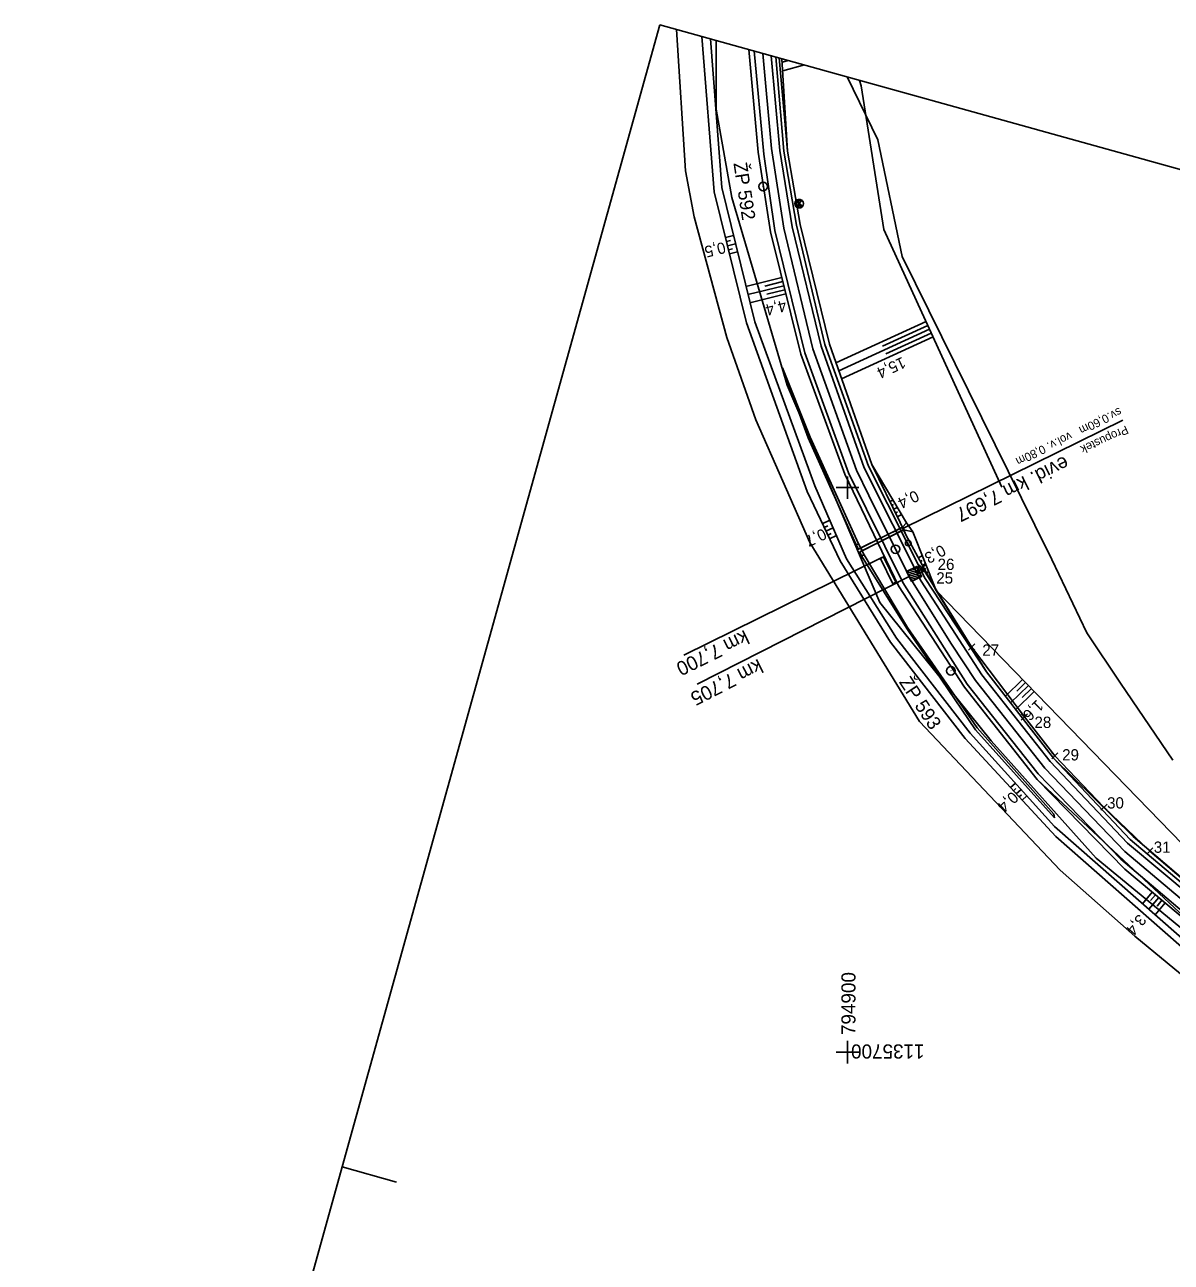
# Model space of a CAD drawing. Extents: x -795046 to -794647, y -1136002 to -1135518.
# Drawn here: x -795045.8 to -794842.7, y -1135737.2 to -1135518 of the extents above; entities that cross this region are included whole.
import ezdxf

# ---------------------------------------------------------------- set-up
doc = ezdxf.new("R2010")
doc.units = 0
for name, color, linetype in [('0381KM005-009P - Vrstva 1', 7, 'Continuous'), ('0381KM005-009P - Vrstva 13', 7, 'Continuous'), ('0381KM005-009P - Vrstva 19', 7, 'Continuous'), ('0381KM005-009P - Vrstva 28', 7, 'Continuous'), ('0381KM005-009P - Vrstva 3', 7, 'Continuous'), ('0381KM005-009P - Vrstva 4', 7, 'Continuous'), ('0381KM005-009P - Vrstva 48', 7, 'Continuous'), ('0381KM005-009P - Vrstva 49', 7, 'Continuous'), ('0381KM005-009P - Vrstva 51', 7, 'Continuous'), ('0381KM005-009P - Vrstva 55', 7, 'Continuous'), ('0381KM005-009P - Vrstva 7', 7, 'Continuous'), ('0381KM005-009P - Vrstva 9', 7, 'Continuous'), ('Default', 7, 'Continuous'), ('formát', 7, 'Continuous'), ('hran DP - hran DP', 7, 'Continuous'), ('krizky_1000 - souradnice', 7, 'Continuous'), ('krizky_1000 - Vrstva 1', 7, 'Continuous'), ('PSR_C2_1_Lomove_body_Strunkovice - Vrstva 60', 7, 'Continuous'), ('PSR_C2_1_trasa_Strunkovice - Kabelová trasa', 7, 'Continuous'), ('vyt_sit - stávající', 7, 'Continuous')]:
    doc.layers.add(name, color=color, linetype=linetype)

msp = doc.modelspace()

# ---------------------------------------------------------------- linework, layer by layer
at = {"layer": '0381KM005-009P - Vrstva 1'}
msp.add_lwpolyline([(-794915, -1135523.08), (-794913.46, -1135539.92), (-794911.29, -1135554.01), (-794906.18, -1135575.42), (-794898.43, -1135596.89), (-794896.25, -1135601.39), (-794889.11, -1135615.73), (-794881.58, -1135627.73), (-794877.36, -1135634.16), (-794865.05, -1135649.67), (-794850.87, -1135664.43), (-794835.06, -1135677.82), (-794817.77, -1135689.58), (-794801.57, -1135698.91), (-794785.04, -1135707.72), (-794765.11, -1135718.4), (-794746.17, -1135729.82), (-794729.27, -1135742.41), (-794716.02, -1135754.58), (-794701.99, -1135770.6), (-794697.2, -1135777.62)], dxfattribs=at)
at = {"layer": '0381KM005-009P - Vrstva 13'}
for points in [[(-794898.09, -1135609.93), (-794898.09, -1135609.93), (-794906.6, -1135591.05), (-794911.52, -1135578.79), (-794907, -1135591.18), (-794898.46, -1135610.15), (-794898.09, -1135609.93)], [(-794897.05, -1135611.89), (-794897.51, -1135612.1), (-794889.51, -1135624.97), (-794877.31, -1135642.92), (-794863.33, -1135658.49)], [(-794863.33, -1135658.49), (-794863.44, -1135657.81), (-794877.06, -1135642.57), (-794889.39, -1135624.78), (-794897.05, -1135611.89)]]:
    msp.add_lwpolyline(points, dxfattribs=at)
at = {"layer": '0381KM005-009P - Vrstva 19'}
for p, q in [((-794890.22, -1135607.23), (-794851.25, -1135588.05)), ((-794898.08, -1135610.9), (-794890.26, -1135606.98)), ((-794890.03, -1135607.47), (-794897.8, -1135611.38)), ((-794890.24, -1135606.98), (-794897.66, -1135610.68)), ((-794897.41, -1135611.19), (-794890.06, -1135607.43))]:
    msp.add_line(p, q, dxfattribs=at)
for points in [[(-794890.7, -1135606.17), (-794890.26, -1135606.98), (-794890.24, -1135606.98), (-794890.06, -1135607.43), (-794890.03, -1135607.47), (-794889.7, -1135608.37)], [(-794898.09, -1135609.93), (-794897.05, -1135611.89), (-794897.51, -1135612.1), (-794897.8, -1135611.38), (-794897.41, -1135611.19), (-794897.66, -1135610.68), (-794898.08, -1135610.9), (-794898.46, -1135610.15)]]:
    msp.add_lwpolyline(points, close=True, dxfattribs=at)
at = {"layer": '0381KM005-009P - Vrstva 28'}
msp.add_line((-794887.06, -1135614.6), (-794887.11, -1135614.51), dxfattribs=at)
msp.add_circle((-794887.08, -1135614.55), 0.5, dxfattribs=at)
at = {"layer": '0381KM005-009P - Vrstva 3'}
for p, q in [((-794889.11, -1135615.73), (-794926.66, -1135634.8)), ((-794886.88, -1135615.74), (-794889.56, -1135614.84)), ((-794887.35, -1135615.97), (-794889.32, -1135615.31)), ((-794887.11, -1135615.26), (-794889.08, -1135614.6)), ((-794887.83, -1135616.21), (-794889.08, -1135615.79)), ((-794888.3, -1135616.45), (-794888.85, -1135616.26)), ((-794887.35, -1135614.79), (-794888.61, -1135614.36)), ((-794887.58, -1135614.31), (-794888.13, -1135614.13))]:
    msp.add_line(p, q, dxfattribs=at)
msp.add_lwpolyline([(-794888.67, -1135616.63), (-794889.56, -1135614.84), (-794887.76, -1135613.95), (-794886.88, -1135615.74)], close=True, dxfattribs=at)
at = {"layer": '0381KM005-009P - Vrstva 4'}
for points in [[(-794917.47, -1135522.4), (-794915.85, -1135540.59), (-794913.67, -1135554.7), (-794908.27, -1135576.33), (-794900.49, -1135597.63), (-794890.98, -1135617.37), (-794879.27, -1135635.32), (-794866.44, -1135651.71), (-794836.69, -1135679.46), (-794818.84, -1135691.63), (-794786.57, -1135709.39), (-794766.3, -1135721.02), (-794748.58, -1135730.93), (-794731.42, -1135743.47), (-794717.51, -1135756.55), (-794703.68, -1135772.07), (-794698, -1135780.52)], [(-794697.72, -1135779.5), (-794703.02, -1135771.54), (-794717.11, -1135755.66), (-794731.12, -1135742.73), (-794748.15, -1135730.35), (-794763.88, -1135720.89), (-794786.11, -1135708.79), (-794818.08, -1135691.13), (-794836.08, -1135678.99), (-794851.61, -1135665.79), (-794866.22, -1135650.67), (-794878.82, -1135634.83), (-794890.24, -1135616.8), (-794899.85, -1135597.37), (-794907.59, -1135576.09), (-794912.87, -1135554.46), (-794914.85, -1135540.94), (-794916.58, -1135522.65)], [(-794696.7, -1135775.84), (-794700.88, -1135769.71), (-794714.51, -1135754.08), (-794728.76, -1135740.91), (-794743.23, -1135730.04), (-794762.73, -1135718.04), (-794783.1, -1135707.11), (-794816.84, -1135688.49), (-794833.24, -1135677.32), (-794850.38, -1135662.96), (-794864.1, -1135648.49), (-794876.22, -1135633.13), (-794886.94, -1135616.58), (-794897.05, -1135596.51), (-794904.69, -1135574.95), (-794909.82, -1135553.82), (-794912.02, -1135540.3), (-794913.51, -1135523.5)], [(-794912.74, -1135523.71), (-794911.32, -1135540.41), (-794909.07, -1135553.52), (-794904.05, -1135574.62), (-794896.27, -1135596.21), (-794886.26, -1135616.08), (-794875.38, -1135632.64), (-794863.5, -1135647.94), (-794849.93, -1135662.35), (-794832.65, -1135676.88), (-794816.85, -1135687.92), (-794782.78, -1135706.49), (-794762.23, -1135717.77), (-794742.47, -1135729.7), (-794727.73, -1135739.54), (-794713.83, -1135753.13), (-794700.2, -1135769.22), (-794696.4, -1135774.74)]]:
    msp.add_lwpolyline(points, dxfattribs=at)
at = {"layer": '0381KM005-009P - Vrstva 48'}
for p, q in [((-794910.48, -1135524.34), (-794911.58, -1135524.64)), ((-794907.65, -1135525.13), (-794911.49, -1135526.17)), ((-794921.65, -1135555.69), (-794920.21, -1135555.33)), ((-794921.47, -1135556.42), (-794920.75, -1135556.24)), ((-794921.29, -1135557.15), (-794919.85, -1135556.79)), ((-794921.11, -1135557.88), (-794920.39, -1135557.7)), ((-794920.93, -1135558.6), (-794919.5, -1135558.25)), ((-794911.66, -1135562.77), (-794918.01, -1135564.35)), ((-794911.47, -1135563.49), (-794914.65, -1135564.29)), ((-794911.29, -1135564.22), (-794917.65, -1135565.81)), ((-794910.93, -1135565.68), (-794917.29, -1135567.27)), ((-794911.11, -1135564.95), (-794914.29, -1135565.74)), ((-794886.1, -1135570.57), (-794902.06, -1135577.88)), ((-794885.48, -1135571.93), (-794901.56, -1135579.3)), ((-794885.79, -1135571.25), (-794893.8, -1135574.92)), ((-794884.85, -1135573.3), (-794901.06, -1135580.72)), ((-794885.17, -1135572.61), (-794893.24, -1135576.31)), ((-794892.51, -1135602.47), (-794891.95, -1135602.19)), ((-794892.18, -1135603.14), (-794891.87, -1135602.99)), ((-794891.85, -1135603.81), (-794891.18, -1135603.49)), ((-794891.52, -1135604.49), (-794891.16, -1135604.31)), ((-794891.19, -1135605.16), (-794890.41, -1135604.78)), ((-794904.48, -1135606.38), (-794903.16, -1135605.75)), ((-794904.16, -1135607.05), (-794903.51, -1135606.74)), ((-794903.83, -1135607.73), (-794902.56, -1135607.12)), ((-794903.51, -1135608.41), (-794902.89, -1135608.11)), ((-794903.19, -1135609.08), (-794901.96, -1135608.5)), ((-794887.47, -1135612.45), (-794886.76, -1135612.05)), ((-794887.11, -1135613.1), (-794886.8, -1135612.93)), ((-794886.75, -1135613.76), (-794886.2, -1135613.46)), ((-794886.39, -1135614.42), (-794886.16, -1135614.29)), ((-794886.03, -1135615.08), (-794885.64, -1135614.87)), ((-794869.01, -1135633.98), (-794872.05, -1135636.93)), ((-794867.96, -1135635.05), (-794871.12, -1135638.12)), ((-794868.48, -1135634.52), (-794870.03, -1135636.02)), ((-794867.44, -1135635.59), (-794869.05, -1135637.16)), ((-794866.92, -1135636.13), (-794870.2, -1135639.31)), ((-794871.13, -1135653.14), (-794870.27, -1135652.34)), ((-794870.62, -1135653.69), (-794870.19, -1135653.29)), ((-794870.11, -1135654.24), (-794869.27, -1135653.46)), ((-794869.6, -1135654.79), (-794869.18, -1135654.4)), ((-794869.09, -1135655.34), (-794868.26, -1135654.56)), ((-794846.02, -1135671.64), (-794847.73, -1135673.69)), ((-794844.87, -1135672.6), (-794846.61, -1135674.68)), ((-794845.45, -1135672.12), (-794846.31, -1135673.15)), ((-794844.3, -1135673.09), (-794845.17, -1135674.13)), ((-794843.72, -1135673.57), (-794845.48, -1135675.67))]:
    msp.add_line(p, q, dxfattribs=at)
at = {"layer": '0381KM005-009P - Vrstva 49'}
for p, q in [((-794912.11, -1135523.89), (-794910.64, -1135540.4)), ((-794890.7, -1135606.17), (-794890.26, -1135606.98)), ((-794890.26, -1135606.98), (-794889.55, -1135606.22)), ((-794890.03, -1135607.47), (-794888.43, -1135607.82)), ((-794889.7, -1135608.37), (-794890.03, -1135607.47))]:
    msp.add_line(p, q, dxfattribs=at)
for points in [[(-794925.83, -1135520.07), (-794923.66, -1135547.6), (-794917.9, -1135570.81), (-794907.19, -1135600.69), (-794901.33, -1135612.99), (-794892.4, -1135627.36), (-794879.19, -1135644.46), (-794863.1, -1135661.78), (-794838.91, -1135683.03), (-794815.97, -1135701.12), (-794794.79, -1135715.61), (-794782.46, -1135721.1), (-794767.75, -1135725.5), (-794750.75, -1135732.17), (-794732.98, -1135744.75), (-794719.14, -1135757.73), (-794705.45, -1135773.64), (-794699.07, -1135784.37)], [(-794749.75, -1135730.99), (-794767.46, -1135724.56), (-794782.23, -1135720.17), (-794794.11, -1135714.55), (-794814.96, -1135700.02), (-794837.43, -1135682.73), (-794863.32, -1135660), (-794878.31, -1135643.5), (-794891.31, -1135626.67), (-794900.17, -1135612.61), (-794905.81, -1135599.68), (-794916.46, -1135570.65), (-794922.29, -1135546.83), (-794924.31, -1135520.49)], [(-794917.47, -1135522.4), (-794915.85, -1135540.59), (-794913.67, -1135554.7), (-794908.27, -1135576.33), (-794900.49, -1135597.63), (-794890.98, -1135617.37), (-794879.27, -1135635.32), (-794866.44, -1135651.71), (-794850.9, -1135667.56)], [(-794911.62, -1135524.02), (-794910.64, -1135540.4), (-794908.42, -1135553.38), (-794903.23, -1135574.56), (-794895.71, -1135595.89), (-794889.55, -1135606.22), (-794888.43, -1135607.82), (-794884.32, -1135618.22)], [(-794897.87, -1135527.85), (-794897.6, -1135528.83), (-794893.57, -1135554.26), (-794872.65, -1135599.94)], [(-794895.71, -1135595.89), (-794890.7, -1135606.17)], [(-794889.7, -1135608.37), (-794884.32, -1135618.22), (-794824.85, -1135679.44), (-794811.36, -1135687.77), (-794786.09, -1135699.38), (-794707.09, -1135741.45)], [(-794863.5, -1135647.94), (-794875.38, -1135632.64), (-794884.32, -1135618.22)], [(-794695.93, -1135773.08), (-794698.78, -1135768.51), (-794712.94, -1135751.52), (-794727.73, -1135739.54), (-794743.72, -1135728.23), (-794763.92, -1135716.02), (-794781.48, -1135706.54), (-794800.89, -1135696.32), (-794816.57, -1135687.28), (-794832.17, -1135676.47), (-794849.4, -1135661.77), (-794863.5, -1135647.94)], [(-794850.9, -1135667.56), (-794836.69, -1135679.46), (-794818.84, -1135691.63), (-794803.16, -1135702.98), (-794784.32, -1135712.45), (-794768.51, -1135721.35), (-794758.17, -1135725.72), (-794749.71, -1135730.94)]]:
    msp.add_lwpolyline(points, dxfattribs=at)
at = {"layer": '0381KM005-009P - Vrstva 51'}
msp.add_lwpolyline([(-794699.07, -1135784.37), (-794705.45, -1135773.64), (-794719.14, -1135757.73), (-794732.98, -1135744.75), (-794750.75, -1135732.17), (-794767.75, -1135725.5), (-794782.46, -1135721.1), (-794794.79, -1135715.61), (-794815.97, -1135701.12), (-794838.91, -1135683.03), (-794863.1, -1135661.78), (-794879.19, -1135644.46), (-794892.4, -1135627.36), (-794901.33, -1135612.99), (-794907.19, -1135600.69), (-794917.9, -1135570.81), (-794923.66, -1135547.6), (-794925.83, -1135520.07)], dxfattribs=at)
at = {"layer": '0381KM005-009P - Vrstva 55'}
msp.add_lwpolyline([(-794930.32, -1135518.82), (-794928.69, -1135543.86), (-794927.18, -1135552.03), (-794921.37, -1135573.41), (-794916.26, -1135587.98), (-794906.67, -1135609.69), (-794887.27, -1135641.42), (-794862.33, -1135667.74), (-794849.1, -1135679.42), (-794837.63, -1135688.88), (-794826.42, -1135697.51), (-794808.25, -1135711.35), (-794792.02, -1135721.49), (-794781.13, -1135725.75), (-794765.57, -1135730.81), (-794749.96, -1135737.95), (-794742.14, -1135743.85), (-794737.72, -1135738.96), (-794727.83, -1135728.01), (-794718.43, -1135717.37), (-794692.54, -1135688.86), (-794715.68, -1135650.06)], dxfattribs=at)
at = {"layer": '0381KM005-009P - Vrstva 7'}
msp.add_line((-794889.24, -1135609.86), (-794889.28, -1135609.77), dxfattribs=at)
for centre, radius in [((-794889.26, -1135609.81), 0.5), ((-794891.51, -1135610.91), 0.75)]:
    msp.add_circle(centre, radius, dxfattribs=at)
at = {"layer": '0381KM005-009P - Vrstva 9'}
for p, q in [((-794893.93, -1135612.39), (-794929, -1135629.69)), ((-794894.19, -1135612.52), (-794894.73, -1135612.79)), ((-794893.66, -1135612.26), (-794894.19, -1135612.52)), ((-794894.19, -1135612.52), (-794892, -1135617.01)), ((-794891.46, -1135616.75), (-794893.66, -1135612.26)), ((-794892, -1135617.01), (-794891.46, -1135616.75))]:
    msp.add_line(p, q, dxfattribs=at)
at = {"layer": 'formát'}
for p, q in [((-794933.28, -1135518), (-794989.53, -1135720.33)), ((-794933.28, -1135518), (-794647.13, -1135597.56)), ((-794989.53, -1135720.33), (-795045.79, -1135922.65)), ((-794989.53, -1135720.33), (-794979.9, -1135723.01))]:
    msp.add_line(p, q, dxfattribs=at)
at = {"layer": 'hran DP - hran DP'}
for p, q in [((-794923.29, -1135532.94), (-794923.3, -1135520.77)), ((-794900.1, -1135527.22), (-794894.63, -1135538.4)), ((-794920.48, -1135548.58), (-794923.29, -1135532.94)), ((-794894.63, -1135538.4), (-794890.34, -1135559.06)), ((-794910.72, -1135581.84), (-794920.48, -1135548.58)), ((-794890.34, -1135559.06), (-794866.81, -1135606.62)), ((-794894.27, -1135620.34), (-794910.72, -1135581.84)), ((-794866.81, -1135606.62), (-794863.8, -1135612.72)), ((-794863.8, -1135612.72), (-794857.64, -1135625.71)), ((-794874.54, -1135644.85), (-794894.27, -1135620.34)), ((-794857.64, -1135625.71), (-794851.67, -1135634.62)), ((-794851.67, -1135634.62), (-794842.4, -1135648.25)), ((-794855.96, -1135665.64), (-794874.54, -1135644.85)), ((-794807.25, -1135705.8), (-794855.96, -1135665.64))]:
    msp.add_line(p, q, dxfattribs=at)
at = {"layer": 'krizky_1000 - Vrstva 1'}
for points in [[(-794900, -1135598), (-794900, -1135602)], [(-794902, -1135600), (-794898, -1135600)], [(-794900, -1135698), (-794900, -1135702)], [(-794902, -1135700), (-794898, -1135700)]]:
    msp.add_lwpolyline(points, dxfattribs=at)
at = {"layer": 'PSR_C2_1_Lomove_body_Strunkovice - Vrstva 60'}
for p, q in [((-794887.54, -1135614.93), (-794886.44, -1135613.83)), ((-794886.44, -1135614.93), (-794887.54, -1135613.83)), ((-794887.3, -1135614.74), (-794886.2, -1135613.64)), ((-794886.2, -1135614.74), (-794887.3, -1135613.64)), ((-794878.58, -1135628.76), (-794877.48, -1135627.66)), ((-794877.48, -1135628.76), (-794878.58, -1135627.66)), ((-794869.23, -1135641.17), (-794868.13, -1135640.07)), ((-794868.13, -1135641.17), (-794869.23, -1135640.07)), ((-794863.83, -1135648.06), (-794862.73, -1135646.96)), ((-794862.73, -1135648.06), (-794863.83, -1135646.96)), ((-794855.13, -1135657.14), (-794854.03, -1135656.04)), ((-794854.03, -1135657.14), (-794855.13, -1135656.04)), ((-794847, -1135664.91), (-794845.9, -1135663.81)), ((-794845.9, -1135664.91), (-794847, -1135663.81))]:
    msp.add_line(p, q, dxfattribs=at)
at = {"layer": 'PSR_C2_1_trasa_Strunkovice - Kabelová trasa'}
for q in [(-794886.99, -1135614.38), (-794878.03, -1135628.21)]:
    msp.add_line((-794886.75, -1135614.19), q, dxfattribs=at)
msp.add_lwpolyline([(-794878.03, -1135628.21), (-794868.68, -1135640.62), (-794863.28, -1135647.51), (-794854.58, -1135656.59), (-794846.45, -1135664.36), (-794833.68, -1135675.27), (-794825.17, -1135681.31), (-794808.45, -1135691.8), (-794797.38, -1135698.09), (-794778.05, -1135708.18), (-794764.25, -1135715.84), (-794749.02, -1135724.95), (-794746.22, -1135726.63)], dxfattribs=at)
at = {"layer": 'vyt_sit - stávající'}
for p, q in [((-794914.98, -1135546.62), (-794914.96, -1135546.72)), ((-794908.58, -1135549.69), (-794909.2, -1135549.24)), ((-794908.46, -1135549.52), (-794909.05, -1135549.09)), ((-794909.02, -1135550.3), (-794908.58, -1135549.69)), ((-794908.4, -1135550.43), (-794908.87, -1135550.09)), ((-794908.28, -1135549.28), (-794908.74, -1135548.94)), ((-794908.1, -1135550.28), (-794908.69, -1135549.85)), ((-794908.13, -1135549.07), (-794908.58, -1135549.69)), ((-794908.58, -1135549.69), (-794907.96, -1135550.14)), ((-794881.72, -1135632.38), (-794881.67, -1135632.47))]:
    msp.add_line(p, q, dxfattribs=at)
for centre, radius in [((-794914.97, -1135546.67), 0.756), ((-794908.58, -1135549.69), 0.764), ((-794881.69, -1135632.43), 0.756)]:
    msp.add_circle(centre, radius, dxfattribs=at)
for radius, start, end in [(0.765, 53.9818, 143.8753), (0.764, 233.293, 323.611)]:
    msp.add_arc((-794908.58, -1135549.69), radius, start, end, dxfattribs=at)

# ---------------------------------------------------------------- texts
at = {"layer": '0381KM005-009P - Vrstva 19'}
for s, height, rotation, p in [('sv.0,60m   vol.v. 0,80m', 1.5, 206.2068, (-794851.86, -1135585.74)), ('Propustek', 1.5, 204.6627, (-794850.69, -1135588.94)), ('evid. km 7,697', 2.5, 206.2068, (-794861.56, -1135594.31))]:
    msp.add_text(s, height=height, rotation=rotation, dxfattribs=at).set_placement(p)
at = {"layer": '0381KM005-009P - Vrstva 3'}
msp.add_text('km 7,705', height=2.5, rotation=206.9201, dxfattribs=at).set_placement((-794915.82, -1135630.27))
at = {"layer": '0381KM005-009P - Vrstva 48'}
for s, rotation, p in [('0,5', 193.9485, (-794921.9, -1135556.44)), ('4,4', 194.0238, (-794911.11, -1135566.74)), ('15,4', 204.6063, (-794890.3, -1135576.77)), ('0,4', 205.994, (-794887.97, -1135600.39)), ('0,7', 205.5118, (-794904.35, -1135607.14)), ('0,3', 208.6712, (-794883.32, -1135610.02)), ('1,6', 224.1646, (-794866.45, -1135637.45)), ('0,4', 222.9053, (-794870.87, -1135653.69)), ('3,4', 230.0673, (-794848.42, -1135675.4))]:
    msp.add_text(s, height=2, rotation=rotation, dxfattribs=at).set_placement(p)
at = {"layer": '0381KM005-009P - Vrstva 9'}
msp.add_text('km 7,700', height=2.5, rotation=206.0861, dxfattribs=at).set_placement((-794918.25, -1135625.14))
at = {"layer": 'Default'}
for s, p in [('26', (-794884.05, -1135614.58)), ('25', (-794884.28, -1135616.99)), ('27', (-794876.13, -1135629.77)), ('28', (-794866.89, -1135642.56)), ('29', (-794861.98, -1135648.32)), ('30', (-794854.02, -1135656.84)), ('31', (-794845.75, -1135664.68))]:
    msp.add_text(s, height=2, dxfattribs=at).set_placement(p)
at = {"layer": 'krizky_1000 - souradnice'}
for s, rotation, p in [('794900', 90, (-794898.6, -1135696.96)), ('1135700', 180, (-794886.37, -1135698.62))]:
    msp.add_text(s, height=2.5, rotation=rotation, dxfattribs=at).set_placement(p)
at = {"layer": 'vyt_sit - stávající'}
for s, rotation, p in [('ŽP 592', 278.77, (-794920.23, -1135542.54)), ('ŽP 593', 303.3346, (-794890.95, -1135634.44))]:
    msp.add_text(s, height=2.4, rotation=rotation, dxfattribs=at).set_placement(p)

doc.saveas('drawing.dxf')
